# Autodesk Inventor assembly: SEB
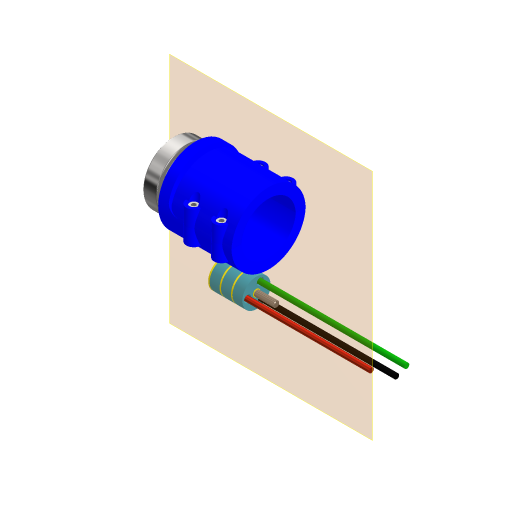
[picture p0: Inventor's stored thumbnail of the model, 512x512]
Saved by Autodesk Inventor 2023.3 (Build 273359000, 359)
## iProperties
Created: 2023-11
Part Number: SEB
Document SubType Name: Assembly
Designer: Thier
Author: Thier
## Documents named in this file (13)
- C:\Travail\BTS TechCom\2-TechnoIndus\21-Meca\214-Systémes Industriels-SI\2141-Pièces Ecrites\21411-Cycle1\214112-TP02Eolienne\2141122-DossierTechniqueEolienne\21411223-Maquette numerique\214112232-CEB-Eolienne\SEB.iam
- C:\Travail\BTS TechCom\2-TechnoIndus\21-Meca\214-Systémes Industriels-SI\2141-Pièces Ecrites\21411-Cycle1\214112-TP02Eolienne\2141122-DossierTechniqueEolienne\21411223-Maquette numerique\214112232-CEB-Eolienne\04-Corps de Pivot.ipt
- C:\Travail\BTS TechCom\2-TechnoIndus\21-Meca\214-Systémes Industriels-SI\2141-Pièces Ecrites\21411-Cycle1\214112-TP02Eolienne\2141122-DossierTechniqueEolienne\21411223-Maquette numerique\214112232-CEB-Eolienne\02-DIN 625 SKF - SKF 6007-2Z.ipt
- C:\Travail\BTS TechCom\2-TechnoIndus\21-Meca\214-Systémes Industriels-SI\2141-Pièces Ecrites\21411-Cycle1\214112-TP02Eolienne\2141122-DossierTechniqueEolienne\21411223-Maquette numerique\214112232-CEB-Eolienne\05-NF E 22-165 - 35x1,75.ipt
- C:\Travail\BTSTEC~1\2-TECH~1\21-Meca\214-SY~1\2141-P~1\21411-~1\214112~1\214112~2\214112~3\214112~2\DISQUE~1\20N-DI~1.IAM
- C:\Travail\BTS TechCom\2-TechnoIndus\21-Meca\214-Systémes Industriels-SI\2141-Pièces Ecrites\21411-Cycle1\214112-TP02Eolienne\2141122-DossierTechniqueEolienne\21411223-Maquette numerique\214112232-CEB-Eolienne\Disque collecteur\20p-Disque Collecteur Phase.iam
- C:\Travail\BTS TechCom\2-TechnoIndus\21-Meca\214-Systémes Industriels-SI\2141-Pièces Ecrites\21411-Cycle1\214112-TP02Eolienne\2141122-DossierTechniqueEolienne\21411223-Maquette numerique\214112232-CEB-Eolienne\Disque collecteur\20t-Disque collecteur Terre.iam
- C:\Travail\BTS TechCom\2-TechnoIndus\21-Meca\214-Systémes Industriels-SI\2141-Pièces Ecrites\21411-Cycle1\214112-TP02Eolienne\2141122-DossierTechniqueEolienne\21411223-Maquette numerique\214112232-CEB-Eolienne\23-Rondelle isolante.ipt
- C:\Travail\BTS TechCom\2-TechnoIndus\21-Meca\214-Systémes Industriels-SI\2141-Pièces Ecrites\21411-Cycle1\214112-TP02Eolienne\2141122-DossierTechniqueEolienne\21411223-Maquette numerique\214112232-CEB-Eolienne\19-Tube isolant.ipt
- C:\Travail\BTS TechCom\2-TechnoIndus\21-Meca\214-Systémes Industriels-SI\2141-Pièces Ecrites\21411-Cycle1\214112-TP02Eolienne\2141122-DossierTechniqueEolienne\21411223-Maquette numerique\214112232-CEB-Eolienne\06-MachoireDePivot.ipt
- C:\Travail\BTS TechCom\2-TechnoIndus\21-Meca\214-Systémes Industriels-SI\2141-Pièces Ecrites\21411-Cycle1\214112-TP02Eolienne\2141122-DossierTechniqueEolienne\21411223-Maquette numerique\214112232-CEB-Eolienne\26-ISO 4032 - M5NF EN.ipt
- C:\Travail\BTS TechCom\2-TechnoIndus\21-Meca\214-Systémes Industriels-SI\2141-Pièces Ecrites\21411-Cycle1\214112-TP02Eolienne\2141122-DossierTechniqueEolienne\21411223-Maquette numerique\214112232-CEB-Eolienne\27-NF E 25-125 - M5 x 30.ipt
- C:\Travail\BTS TechCom\2-TechnoIndus\21-Meca\214-Systémes Industriels-SI\2141-Pièces Ecrites\21411-Cycle1\214112-TP02Eolienne\2141122-DossierTechniqueEolienne\21411223-Maquette numerique\214112232-CEB-Eolienne\25-NF E 25-130 - M6 x 55A.ipt
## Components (20 placed, 12 different names)
1. 04-Corps de Pivot:1
2. NF E 22-165 35x1,75:1 — Logement:1
3. 20p-Disque Collecteur Phase:1 [sub-assembly] — Logement:38, Logement:39, Logement:44, Logement:45
4. 20t-Disque collecteur Terre:1 [sub-assembly] — Logement:42, Logement:43
5. 23-Rondelle isolante:1 — Logement:40, Logement:41, Logement:44, Logement:45
6. 23-Rondelle isolante:2 — Logement:38, Logement:39, Logement:48, Logement:49
7. 23-Rondelle isolante:3 — Logement:42, Logement:43, Logement:46, Logement:47
8. 19-Tube isolant:1 — Logement:49
9. 06-MachoireDePivot:1 — Logement:15, Logement:16, Logement:17, Logement:18, Logement:19, Logement:20
10. NF E 25-125 M5 x 30:4 — Logement:20
11. NF E 25-125 M5 x 30:3 — Logement:19
12. NF E 25-125 M5 x 30:2 — Logement:18
13. NF E 25-125 M5 x 30:1 — Logement:17
14. NF EN 24032 M5:1 — Logement:22
15. NF EN 24032 M5:4 — Angle:1, Logement:21
16. NF EN 24032 M5:5 — Logement:24
17. NF EN 24032 M5:6 — Logement:23
18. 20N-DI~1:1 [sub-assembly] — Logement:40, Logement:41, Logement:46, Logement:47
19. DIN 625 SKF- avec deux flasques Z SKF 6007-2Z:1 — Logement:35
20. NF E 25-130 - A M6 x 55:1 — Logement:48
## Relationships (25: Insert 24, Angle 1)
- Logement:1 [Insert]: NF E 22-165 35x1,75:1
- Logement:15 [Insert]: 06-MachoireDePivot:1
- Logement:16 [Insert]: 06-MachoireDePivot:1
- Logement:17 [Insert]: 06-MachoireDePivot:1 ↔ NF E 25-125 M5 x 30:1
- Logement:18 [Insert]: 06-MachoireDePivot:1 ↔ NF E 25-125 M5 x 30:2
- Logement:19 [Insert]: 06-MachoireDePivot:1 ↔ NF E 25-125 M5 x 30:3
- Logement:20 [Insert]: 06-MachoireDePivot:1 ↔ NF E 25-125 M5 x 30:4
- Angle:1: NF EN 24032 M5:4
- Logement:21 [Insert]: NF EN 24032 M5:4
- Logement:22 [Insert]: NF EN 24032 M5:1
- Logement:23 [Insert]: NF EN 24032 M5:6
- Logement:24 [Insert]: NF EN 24032 M5:5
- Logement:35 [Insert]: DIN 625 SKF- avec deux flasques Z SKF 6007-2Z:1
- Logement:38 [Insert]: 20p-Disque Collecteur Phase:1 ↔ 23-Rondelle isolante:2
- Logement:39 [Insert]: 20p-Disque Collecteur Phase:1 ↔ 23-Rondelle isolante:2
- Logement:40 [Insert]: 23-Rondelle isolante:1 ↔ 20N-DI~1:1
- Logement:41 [Insert]: 23-Rondelle isolante:1 ↔ 20N-DI~1:1
- Logement:42 [Insert]: 20t-Disque collecteur Terre:1 ↔ 23-Rondelle isolante:3
- Logement:43 [Insert]: 20t-Disque collecteur Terre:1 ↔ 23-Rondelle isolante:3
- Logement:44 [Insert]: 20p-Disque Collecteur Phase:1 ↔ 23-Rondelle isolante:1
- Logement:45 [Insert]: 20p-Disque Collecteur Phase:1 ↔ 23-Rondelle isolante:1
- Logement:46 [Insert]: 23-Rondelle isolante:3 ↔ 20N-DI~1:1
- Logement:47 [Insert]: 23-Rondelle isolante:3 ↔ 20N-DI~1:1
- Logement:48 [Insert]: 23-Rondelle isolante:2 ↔ NF E 25-130 - A M6 x 55:1
- Logement:49 [Insert]: 23-Rondelle isolante:2 ↔ 19-Tube isolant:1
